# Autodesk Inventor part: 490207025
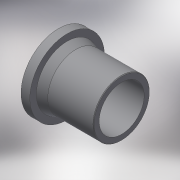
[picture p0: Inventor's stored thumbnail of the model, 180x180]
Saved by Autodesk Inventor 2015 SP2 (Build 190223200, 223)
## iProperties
Created: 2017-07
Part Number: 490207025
Material: Generic
Description: Stub Flange 25
Document SubType Name: Modeling
Designer: Кирилл
Mass: 39.7601 g
Surface Area: 178.07 cm^2
Volume: 39.7601 cm^3
Density: 1 g/cm^3
Appearance: Default
Author: Кирилл
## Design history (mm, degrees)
derived "490207.ipt"
feature "Solid1::490207.ipt"
tag "TaggingFeature1"
body "Solid1"
other parameters: "d0" = 85, "d1" = 32, "d2" = 25, "d4" = 58, "d5" = 9, "d16" = 25, "d17" = 0.5, "d18" = 0.5, "d19" = 0.5, "d21" = 0.5, "d24" = 0.5, "d25" = 0.5, "d26" = 0.25, "d27" = 0, "d32" = 0.25, "d_" = 25, "L_" = 85, "D_" = 58, "D_1" = 32, "a_" = 9
